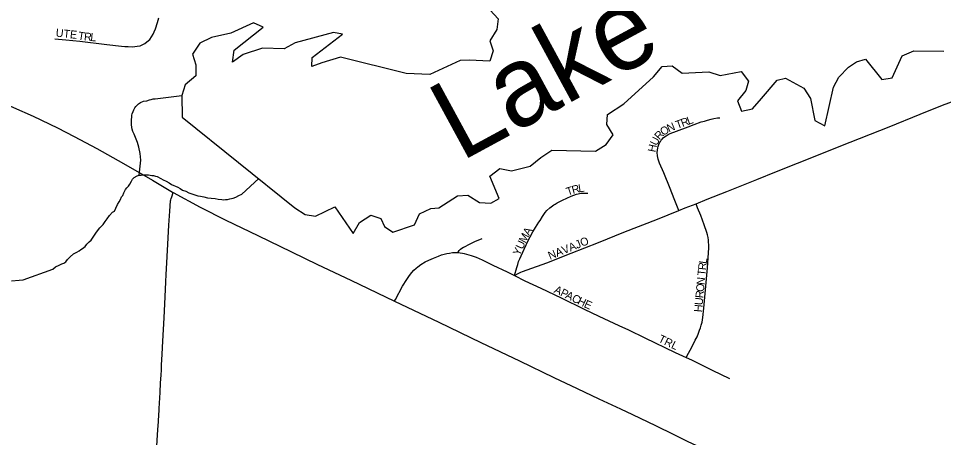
# Model space of a CAD drawing. Extents: x -49 to -8.2, y 9.4 to 23.5.
# Drawn here: x -46.008 to -45.461, y 18.265 to 18.513 of the extents above; entities that cross this region are included whole.
import ezdxf

# ---------------------------------------------------------------- set-up
doc = ezdxf.new("R2010")
doc.units = 0
for name, color, linetype in [('GM_X_County_Road', 7, 'Continuous'), ('GM_X_Major_Lake', 7, 'Continuous'), ('GM_X_Major_Lake_Text', 7, 'Continuous'), ('GM_X_Major_River', 7, 'Continuous'), ('GM_X_Township_Road', 7, 'Continuous'), ('GM_X_Township_Subdivision', 7, 'Continuous'), ('GM_X_Township_Subdivision_Text', 7, 'Continuous')]:
    doc.layers.add(name, color=color, linetype=linetype)

msp = doc.modelspace()

# ---------------------------------------------------------------- linework, layer by layer
at = {"layer": 'GM_X_County_Road'}
for points in [[(-46.07301, 18.48719), (-46.06276, 18.48265), (-46.04407, 18.47422), (-46.02697, 18.46682), (-46.01131, 18.45998), (-45.99972, 18.45472), (-45.98544, 18.44786), (-45.97549, 18.44276), (-45.96209, 18.43554), (-45.9464, 18.42667), (-45.92914, 18.41679), (-45.91736, 18.40986), (-45.91688, 18.4096)], [(-45.91688, 18.4096), (-45.901, 18.40096), (-45.88585, 18.3932), (-45.86681, 18.38409), (-45.84694, 18.37455), (-45.83162, 18.36702), (-45.81199, 18.35767), (-45.78599, 18.34534)], [(-45.78599, 18.34534), (-45.78224, 18.34356), (-45.75978, 18.33292), (-45.73492, 18.32083), (-45.71225, 18.30991), (-45.69179, 18.30015), (-45.67801, 18.29367), (-45.66516, 18.28752), (-45.65249, 18.28165), (-45.64523, 18.27813), (-45.63178, 18.27172), (-45.62092, 18.26635), (-45.61255, 18.26227), (-45.59515, 18.25405), (-45.56651, 18.24049), (-45.5508, 18.23301), (-45.52386, 18.22021), (-45.51432, 18.21567), (-45.5037, 18.21051), (-45.49086, 18.20426), (-45.48021, 18.19917), (-45.47487, 18.19665), (-45.46563, 18.19223), (-45.4631, 18.19099)]]:
    msp.add_lwpolyline(points, dxfattribs=at)
at = {"layer": 'GM_X_Major_Lake'}
for points in [[(-45.73449, 18.52285), (-45.72468, 18.51239), (-45.72558, 18.50614), (-45.72971, 18.4994), (-45.72776, 18.49348), (-45.7296, 18.48726), (-45.74191, 18.48791), (-45.74722, 18.48765), (-45.76522, 18.47951), (-45.77923, 18.48), (-45.81807, 18.48959), (-45.82895, 18.48641)], [(-45.82895, 18.48641), (-45.83506, 18.48408), (-45.83475, 18.48957), (-45.81682, 18.50322), (-45.8221, 18.50429), (-45.8448, 18.49815), (-45.85132, 18.49468), (-45.8642, 18.49497), (-45.87566, 18.49124), (-45.88182, 18.48682), (-45.88091, 18.49382), (-45.86373, 18.50748), (-45.86955, 18.51007), (-45.88277, 18.50391), (-45.89439, 18.50132), (-45.90129, 18.49787), (-45.9056, 18.49152), (-45.90366, 18.48521), (-45.90362, 18.47857), (-45.9098, 18.4734), (-45.91184, 18.46699), (-45.91156, 18.45408)], [(-45.84508, 18.40044), (-45.83891, 18.39651), (-45.83287, 18.39562), (-45.82137, 18.40105), (-45.81054, 18.38526), (-45.80679, 18.39182), (-45.80006, 18.39622), (-45.79423, 18.3942), (-45.79206, 18.3894), (-45.78702, 18.38607), (-45.77422, 18.39053), (-45.77123, 18.39691), (-45.76452, 18.40018), (-45.75978, 18.40046), (-45.74881, 18.40762), (-45.74274, 18.40805), (-45.73582, 18.40373), (-45.72901, 18.4032), (-45.72421, 18.40594), (-45.7296, 18.41934), (-45.72381, 18.42376), (-45.71683, 18.42247), (-45.70577, 18.42526), (-45.69959, 18.43025), (-45.69305, 18.43466), (-45.66728, 18.43409), (-45.66094, 18.43794), (-45.65683, 18.44373), (-45.66049, 18.44988), (-45.66017, 18.45575), (-45.65036, 18.46199), (-45.63294, 18.47811), (-45.62769, 18.48407), (-45.6218, 18.48451), (-45.61602, 18.48021), (-45.60027, 18.481), (-45.5935, 18.47876), (-45.58113, 18.48115), (-45.5767, 18.47555), (-45.57834, 18.46989), (-45.58322, 18.46393), (-45.58089, 18.45781), (-45.57441, 18.45918), (-45.56897, 18.46513), (-45.55982, 18.47613), (-45.55486, 18.47734), (-45.544, 18.47141), (-45.53997, 18.46525), (-45.53742, 18.45211), (-45.53161, 18.44913), (-45.52655, 18.47198), (-45.52339, 18.47779), (-45.51757, 18.48373), (-45.51276, 18.48685), (-45.5076, 18.48845), (-45.49783, 18.47647), (-45.49174, 18.47748), (-45.48576, 18.49044), (-45.47887, 18.49351), (-45.46124, 18.49331)], [(-45.91156, 18.45408), (-45.84508, 18.40044)]]:
    msp.add_lwpolyline(points, dxfattribs=at)
at = {"layer": 'GM_X_Major_River'}
for points in [[(-45.93703, 18.41992), (-45.93599, 18.42864), (-45.93652, 18.43264), (-45.93723, 18.43644), (-45.93797, 18.43911), (-45.93852, 18.44025), (-45.93926, 18.44216), (-45.94, 18.44407), (-45.94074, 18.44578), (-45.9413, 18.44712), (-45.94148, 18.44807), (-45.94165, 18.44978), (-45.94163, 18.45168), (-45.9414, 18.45529), (-45.9412, 18.45623), (-45.94062, 18.45756), (-45.94023, 18.4585), (-45.93965, 18.45964), (-45.93907, 18.46058), (-45.93753, 18.46208), (-45.9362, 18.46283), (-45.93448, 18.46357), (-45.93258, 18.46393), (-45.93087, 18.46448), (-45.92992, 18.46466), (-45.92878, 18.46503), (-45.92764, 18.46502), (-45.91184, 18.46699)], [(-46.00576, 18.35781), (-45.98809, 18.36424), (-45.98656, 18.36555), (-45.98446, 18.36667), (-45.98274, 18.36741), (-45.9816, 18.36778), (-45.98045, 18.36853), (-45.97949, 18.36985), (-45.97795, 18.37154), (-45.97585, 18.37323), (-45.97394, 18.37435), (-45.9726, 18.37509), (-45.97165, 18.37584), (-45.9705, 18.3764), (-45.96897, 18.37771), (-45.96801, 18.37903), (-45.96667, 18.38035), (-45.96552, 18.38129), (-45.96263, 18.38543), (-45.96166, 18.38694), (-45.96032, 18.38864), (-45.9584, 18.39071), (-45.95724, 18.3924), (-45.9559, 18.39391), (-45.95455, 18.39598), (-45.95282, 18.39786), (-45.95167, 18.39861), (-45.9509, 18.40031), (-45.94993, 18.40239), (-45.94896, 18.40409), (-45.94819, 18.40541), (-45.9476, 18.40711), (-45.94664, 18.40786), (-45.94606, 18.40938), (-45.94509, 18.41127), (-45.94432, 18.4124), (-45.94336, 18.41334), (-45.94259, 18.41447), (-45.94162, 18.41636), (-45.94104, 18.41749), (-45.94008, 18.41843), (-45.93817, 18.41955), (-45.93703, 18.41992), (-45.93589, 18.41991), (-45.93475, 18.42008), (-45.9338, 18.42007), (-45.93266, 18.42006), (-45.93152, 18.42005), (-45.93058, 18.41985), (-45.92963, 18.41965), (-45.92868, 18.41964), (-45.92736, 18.41925), (-45.92641, 18.41905), (-45.92434, 18.41789), (-45.92283, 18.41711), (-45.92113, 18.41633), (-45.91943, 18.41537), (-45.91792, 18.4144), (-45.91414, 18.41265), (-45.91282, 18.41188), (-45.91151, 18.41091), (-45.90942, 18.41032), (-45.90773, 18.40936), (-45.90584, 18.40877), (-45.90413, 18.40818), (-45.90243, 18.40759), (-45.90073, 18.40738), (-45.89883, 18.40698), (-45.89675, 18.40639), (-45.89448, 18.40618), (-45.8922, 18.40597), (-45.89031, 18.40557), (-45.88822, 18.40535), (-45.88708, 18.40534), (-45.88594, 18.40552), (-45.88481, 18.40551), (-45.88347, 18.40587), (-45.88252, 18.40605), (-45.88157, 18.40623), (-45.87986, 18.40679), (-45.87814, 18.40791), (-45.87642, 18.40865), (-45.86623, 18.41787)], [(-46.01264, 18.35728), (-46.00808, 18.35761), (-46.00576, 18.35781)]]:
    msp.add_lwpolyline(points, dxfattribs=at)
at = {"layer": 'GM_X_Township_Road'}
msp.add_lwpolyline([(-45.92717, 18.24955), (-45.92616, 18.26625), (-45.92583, 18.27182), (-45.92571, 18.27367), (-45.92563, 18.27491), (-45.92547, 18.27738), (-45.92525, 18.2811), (-45.92522, 18.28172), (-45.92469, 18.29132), (-45.92437, 18.29689), (-45.9241, 18.30154), (-45.92393, 18.30464), (-45.92382, 18.30743), (-45.92347, 18.31394), (-45.92307, 18.32169), (-45.92237, 18.33545), (-45.92173, 18.34775), (-45.9213, 18.35673), (-45.92108, 18.36106), (-45.92094, 18.36447), (-45.92013, 18.37901), (-45.91944, 18.39016), (-45.91896, 18.39852), (-45.91851, 18.4047), (-45.9184, 18.40533), (-45.91822, 18.40601), (-45.91782, 18.40709), (-45.91688, 18.4096)], dxfattribs=at)
at = {"layer": 'GM_X_Township_Subdivision'}
for points in [[(-45.98701, 18.50055), (-45.98052, 18.49991), (-45.97219, 18.49907), (-45.95621, 18.49714), (-45.94758, 18.49625), (-45.94549, 18.49608), (-45.94362, 18.49597), (-45.94108, 18.49588), (-45.9383, 18.49613), (-45.93646, 18.49648), (-45.93486, 18.49714), (-45.93374, 18.49784), (-45.93247, 18.49873), (-45.93086, 18.50021), (-45.92969, 18.50166), (-45.92877, 18.50327), (-45.92816, 18.50463), (-45.92745, 18.50642), (-45.92615, 18.51026), (-45.92536, 18.51293)], [(-45.60775, 18.40296), (-45.6011, 18.40558), (-45.58956, 18.4102), (-45.58264, 18.41295), (-45.57181, 18.41729), (-45.56017, 18.42196), (-45.53541, 18.43191), (-45.52216, 18.43724), (-45.49358, 18.44849), (-45.47516, 18.45585), (-45.46196, 18.46123), (-45.45442, 18.46408), (-45.45118, 18.46509), (-45.44785, 18.4661), (-45.4445, 18.4669), (-45.44107, 18.46743), (-45.43764, 18.46776)], [(-45.61787, 18.39895), (-45.61826, 18.39995), (-45.6206, 18.40584), (-45.62307, 18.41205), (-45.62683, 18.42121), (-45.62927, 18.42692), (-45.63007, 18.42927), (-45.63034, 18.43028), (-45.63056, 18.43138), (-45.63071, 18.43324), (-45.63063, 18.43455), (-45.63038, 18.43608), (-45.63014, 18.4369), (-45.62976, 18.43792), (-45.62931, 18.43891), (-45.62886, 18.43973), (-45.62836, 18.44051), (-45.62775, 18.44121), (-45.62715, 18.44192), (-45.62639, 18.44257), (-45.62544, 18.44322), (-45.62425, 18.44393), (-45.623, 18.4446), (-45.61936, 18.44594), (-45.61234, 18.44853), (-45.60881, 18.44983), (-45.60475, 18.45132), (-45.6028, 18.4519), (-45.60105, 18.45244), (-45.59876, 18.45304), (-45.59726, 18.45337), (-45.59514, 18.45372), (-45.59361, 18.45374)], [(-45.71515, 18.36042), (-45.71371, 18.36512), (-45.71321, 18.36702), (-45.71269, 18.36868), (-45.71203, 18.37035), (-45.70948, 18.37603), (-45.70676, 18.38161), (-45.70592, 18.38326), (-45.70431, 18.38623), (-45.70272, 18.38889), (-45.70071, 18.39202), (-45.69999, 18.39304), (-45.69852, 18.3954), (-45.69697, 18.39769), (-45.69595, 18.39886), (-45.69414, 18.40056), (-45.69189, 18.40221), (-45.69112, 18.40271), (-45.68982, 18.40353), (-45.68678, 18.40508), (-45.68166, 18.40733), (-45.67845, 18.40853), (-45.67575, 18.4092), (-45.67421, 18.40929), (-45.67268, 18.40926), (-45.67207, 18.40925), (-45.67178, 18.40918)], [(-45.61787, 18.39895), (-45.61409, 18.40046), (-45.60775, 18.40296)], [(-45.61368, 18.31195), (-45.61347, 18.31235), (-45.60995, 18.31844), (-45.6082, 18.32212), (-45.60716, 18.32424), (-45.60627, 18.32636), (-45.60564, 18.32802), (-45.60509, 18.32957), (-45.60465, 18.33115), (-45.60419, 18.33286), (-45.60391, 18.33427), (-45.6037, 18.33561), (-45.60308, 18.34117), (-45.60235, 18.34983), (-45.601, 18.36499), (-45.6002, 18.37676), (-45.60021, 18.37857), (-45.60029, 18.38017), (-45.60042, 18.38145), (-45.60064, 18.38295), (-45.60095, 18.38445), (-45.6014, 18.38595), (-45.60285, 18.39038), (-45.60499, 18.39588), (-45.60679, 18.40051), (-45.60775, 18.40296)], [(-45.71515, 18.36042), (-45.71476, 18.36064), (-45.71328, 18.36149), (-45.71259, 18.36188), (-45.71141, 18.36244), (-45.71036, 18.36284), (-45.70763, 18.36383), (-45.69599, 18.36797), (-45.68161, 18.37374), (-45.66543, 18.38001), (-45.65046, 18.38604), (-45.63053, 18.3939), (-45.61787, 18.39895)], [(-45.74848, 18.37409), (-45.7484, 18.37425), (-45.74783, 18.37524), (-45.74744, 18.37565), (-45.74697, 18.37604), (-45.74617, 18.3766), (-45.74533, 18.37717), (-45.74468, 18.37753), (-45.74392, 18.37791), (-45.74252, 18.37859), (-45.73857, 18.3805), (-45.73427, 18.3824)], [(-45.78599, 18.34534), (-45.78548, 18.34629), (-45.78127, 18.35414), (-45.77886, 18.35817), (-45.77724, 18.36047), (-45.77588, 18.3622), (-45.7746, 18.36358), (-45.77335, 18.36476), (-45.77225, 18.36569), (-45.77048, 18.36702), (-45.76788, 18.36851), (-45.76577, 18.36954), (-45.76294, 18.37074), (-45.76003, 18.37197), (-45.75823, 18.37262), (-45.75678, 18.37307), (-45.7552, 18.37347), (-45.7535, 18.37376), (-45.75178, 18.37401), (-45.74956, 18.37415), (-45.74848, 18.37409)], [(-45.74848, 18.37409), (-45.74721, 18.37397), (-45.74594, 18.37375), (-45.74484, 18.37353), (-45.74064, 18.37234), (-45.73775, 18.37122), (-45.73425, 18.36973), (-45.72786, 18.36656), (-45.71943, 18.36259), (-45.71515, 18.36042)], [(-45.71515, 18.36042), (-45.7089, 18.35725), (-45.69963, 18.35288), (-45.68753, 18.3472), (-45.67382, 18.34057), (-45.66518, 18.33637), (-45.65336, 18.33092), (-45.64776, 18.32824), (-45.63795, 18.32353), (-45.62009, 18.31496), (-45.61368, 18.31195)], [(-45.61368, 18.31195), (-45.61052, 18.31047), (-45.59819, 18.30451), (-45.58793, 18.29955)]]:
    msp.add_lwpolyline(points, dxfattribs=at)

# ---------------------------------------------------------------- texts
at = {"layer": 'GM_X_Major_Lake_Text'}
msp.add_text('Lake', height=0.047346, rotation=28.5136, dxfattribs=at).set_placement((-45.74693, 18.42757))
at = {"layer": 'GM_X_Township_Subdivision_Text'}
for s, height, rotation, p in [('UTE', 0.004735, 353.6554, (-45.98661, 18.50189)), ('T', 0.00473, 351.2788, (-45.97346, 18.50018)), ('R', 0.00473, 354.7573, (-45.96986, 18.49963)), ('L', 0.00473, 355.0166, (-45.9661, 18.49929)), ('T', 0.00473, 19.9901, (-45.61888, 18.44719)), ('R', 0.00473, 19.9847, (-45.61575, 18.44833)), ('L', 0.00473, 19.997, (-45.61222, 18.44961)), ('R', 0.00473, 48.5399, (-45.62933, 18.44035)), ('O', 0.00473, 33.8174, (-45.62708, 18.44295)), ('N', 0.00473, 22.7796, (-45.62384, 18.44516)), ('U', 0.00473, 63.0049, (-45.63104, 18.4369)), ('H', 0.00473, 78.3342, (-45.63177, 18.43314)), ('T', 0.00473, 17.9164, (-45.68367, 18.40768)), ('R', 0.00473, 15.385, (-45.68055, 18.40869)), ('L', 0.00473, 8.0605, (-45.67709, 18.40965)), ('M', 0.00473, 63.0685, (-45.70864, 18.37932)), ('A', 0.00473, 60.3744, (-45.70641, 18.38373)), ('U', 0.00473, 65.3119, (-45.71036, 18.37558)), ('NAVAJO', 0.004735, 21.9903, (-45.69413, 18.36975)), ('Y', 0.00473, 65.3119, (-45.7121, 18.37179)), ('L', 0.00473, 82.4649, (-45.60151, 18.36716)), ('T', 0.00473, 84.6298, (-45.60224, 18.36016)), ('R', 0.00473, 83.5016, (-45.60193, 18.36345)), ('N', 0.00473, 84.6374, (-45.60274, 18.35476)), ('A', 0.00473, 334.0216, (-45.69215, 18.35055)), ('P', 0.00473, 334.0092, (-45.6884, 18.34873)), ('O', 0.00473, 84.6312, (-45.60313, 18.35062)), ('A', 0.00473, 334.0291, (-45.68541, 18.34727)), ('C', 0.00473, 334.0105, (-45.68166, 18.34544)), ('H', 0.00473, 334.0291, (-45.67829, 18.3438)), ('R', 0.00473, 84.6253, (-45.60348, 18.34688)), ('E', 0.00473, 335.54, (-45.67442, 18.34192)), ('H', 0.00473, 84.6374, (-45.60426, 18.33859)), ('U', 0.00473, 84.6312, (-45.60387, 18.34273)), ('TRL', 0.004735, 334.4471, (-45.63049, 18.32139))]:
    msp.add_text(s, height=height, rotation=rotation, dxfattribs=at).set_placement(p)

doc.saveas('drawing.dxf')
